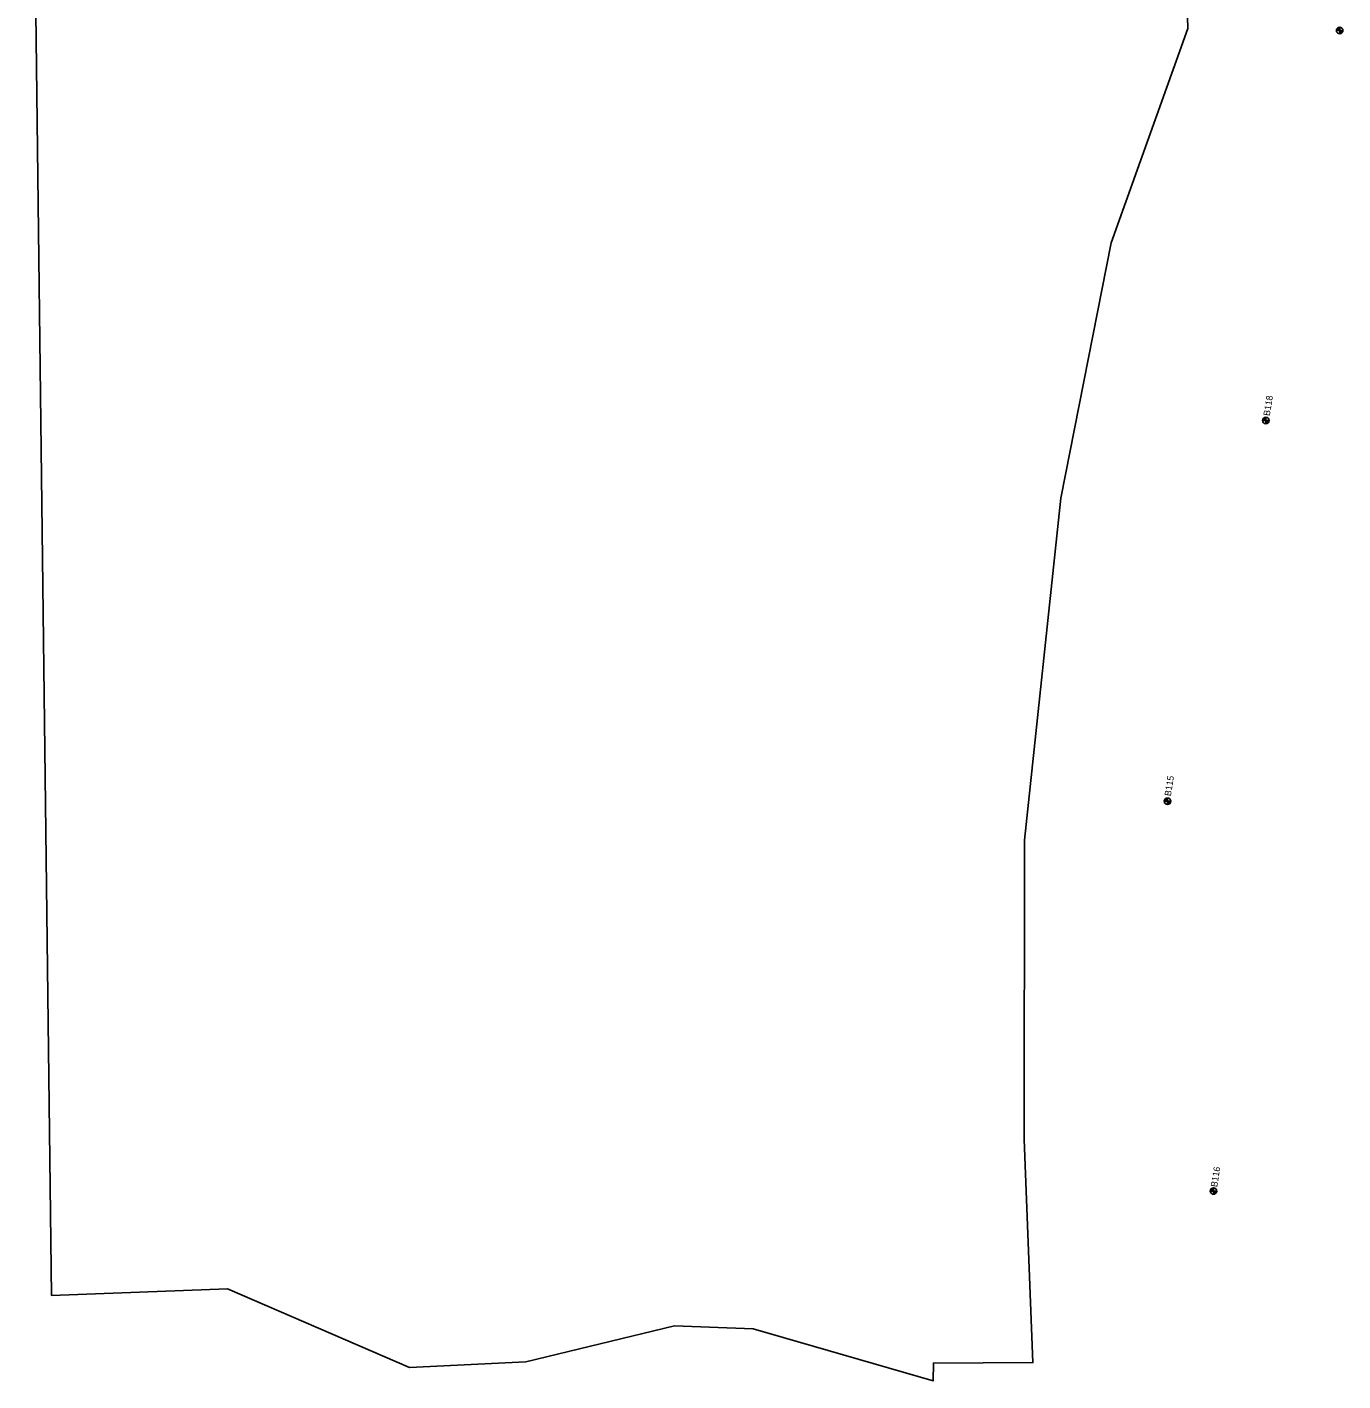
# Model space of a CAD drawing. Extents: x 331323 to 388339, y 121519 to 205315.
# Drawn here: x 353385 to 355399, y 191699 to 193771 of the extents above; entities that cross this region are included whole.
import ezdxf

# ---------------------------------------------------------------- set-up
doc = ezdxf.new("R2010")
doc.units = 0
for name, color, linetype in [('E_SOIL_BORE1 [KAPUR_CADDS_LEVELS]', 7, 'Continuous'), ('E_SOIL_BORE2 [KAPUR_CADDS_LEVELS]', 7, 'Continuous'), ('Level 21', 7, 'Continuous'), ('P_MARK', 7, 'Continuous')]:
    doc.layers.add(name, color=color, linetype=linetype)

msp = doc.modelspace()

# ---------------------------------------------------------------- linework, layer by layer
at = {"layer": 'Level 21'}
msp.add_lwpolyline([(355146.4, 194286.1), (355161.2, 193768.9), (355044, 193440.7), (354967.1, 193050.1), (354911.4, 192526.4), (354910.9, 192068.3), (354924.3, 191726.6), (354771.9, 191725.9), (354771.4, 191698.6), (354496.1, 191778.1), (354375.9, 191783.1), (354148.1, 191727.6), (353970.2, 191718.9), (353691.7, 191839.8), (353422.4, 191829.2), (353385, 194880.4)], dxfattribs=at)
at = {"layer": 'P_MARK'}
for p, q in [((355388.6, 193765.9), (355398.6, 193765.9)), ((355393.6, 193770.9), (355393.6, 193760.9)), ((355280.6, 193173.8), (355280.6, 193163.8)), ((355275.6, 193168.8), (355285.6, 193168.8)), ((355125.2, 192585.9), (355135.2, 192585.9)), ((355130.2, 192590.9), (355130.2, 192580.9)), ((355200.5, 191994.3), (355200.5, 191984.3)), ((355195.5, 191989.3), (355205.5, 191989.3))]:
    msp.add_line(p, q, dxfattribs=at)
for centre in [(355393.6, 193765.9), (355280.6, 193168.8), (355130.2, 192585.9), (355200.5, 191989.3)]:
    msp.add_circle(centre, 5, dxfattribs=at)
for centre, radius, start, end in [((355393.6, 193765.9), 4.5, 89.9869, 179.9869), ((355393.6, 193765.9), 4, 89.9869, 179.9869), ((355393.6, 193765.9), 3.5, 89.9869, 179.9869), ((355393.6, 193765.9), 3, 89.9869, 179.9869), ((355393.6, 193765.9), 2.5, 89.9869, 179.9869), ((355393.6, 193765.9), 2, 89.9869, 179.9869), ((355393.6, 193765.9), 1.5, 89.9869, 179.9869), ((355393.6, 193765.9), 1, 89.9869, 179.9869), ((355393.6, 193765.9), 0.5, 89.9869, 179.9869), ((355393.6, 193765.9), 4.5, 269.9869, 359.9869), ((355393.6, 193765.9), 4, 269.9869, 359.9869), ((355393.6, 193765.9), 3.5, 269.9869, 359.9869), ((355393.6, 193765.9), 3, 269.9869, 359.9869), ((355393.6, 193765.9), 2.5, 269.9869, 359.9869), ((355393.6, 193765.9), 2, 269.9869, 359.9869), ((355393.6, 193765.9), 1.5, 269.9869, 359.9869), ((355393.6, 193765.9), 1, 269.9869, 359.9869), ((355393.6, 193765.9), 0.5, 269.9869, 359.9869), ((355280.6, 193168.8), 4.5, 89.9869, 179.9869), ((355280.6, 193168.8), 4, 89.9869, 179.9869), ((355280.6, 193168.8), 3.5, 89.9869, 179.9869), ((355280.6, 193168.8), 3, 89.9869, 179.9869), ((355280.6, 193168.8), 2.5, 89.9869, 179.9869), ((355280.6, 193168.8), 2, 89.9869, 179.9869), ((355280.6, 193168.8), 1.5, 89.9869, 179.9869), ((355280.6, 193168.8), 1, 89.9869, 179.9869), ((355280.6, 193168.8), 0.5, 89.9869, 179.9869), ((355280.6, 193168.8), 4.5, 269.9869, 359.9869), ((355280.6, 193168.8), 4, 269.9869, 359.9869), ((355280.6, 193168.8), 3.5, 269.9869, 359.9869), ((355280.6, 193168.8), 3, 269.9869, 359.9869), ((355280.6, 193168.8), 2.5, 269.9869, 359.9869), ((355280.6, 193168.8), 2, 269.9869, 359.9869), ((355280.6, 193168.8), 1.5, 269.9869, 359.9869), ((355280.6, 193168.8), 1, 269.9869, 359.9869), ((355280.6, 193168.8), 0.5, 269.9869, 359.9869), ((355130.2, 192585.9), 4.5, 89.9869, 179.9869), ((355130.2, 192585.9), 4, 89.9869, 179.9869), ((355130.2, 192585.9), 3.5, 89.9869, 179.9869), ((355130.2, 192585.9), 3, 89.9869, 179.9869), ((355130.2, 192585.9), 2.5, 89.9869, 179.9869), ((355130.2, 192585.9), 2, 89.9869, 179.9869), ((355130.2, 192585.9), 1.5, 89.9869, 179.9869), ((355130.2, 192585.9), 1, 89.9869, 179.9869), ((355130.2, 192585.9), 0.5, 89.9869, 179.9869), ((355130.2, 192585.9), 4.5, 269.9869, 359.9869), ((355130.2, 192585.9), 4, 269.9869, 359.9869), ((355130.2, 192585.9), 3.5, 269.9869, 359.9869), ((355130.2, 192585.9), 3, 269.9869, 359.9869), ((355130.2, 192585.9), 2.5, 269.9869, 359.9869), ((355130.2, 192585.9), 2, 269.9869, 359.9869), ((355130.2, 192585.9), 1.5, 269.9869, 359.9869), ((355130.2, 192585.9), 1, 269.9869, 359.9869), ((355130.2, 192585.9), 0.5, 269.9869, 359.9869), ((355200.5, 191989.3), 4.5, 89.9869, 179.9869), ((355200.5, 191989.3), 4, 89.9869, 179.9869), ((355200.5, 191989.3), 3.5, 89.9869, 179.9869), ((355200.5, 191989.3), 3, 89.9869, 179.9869), ((355200.5, 191989.3), 2.5, 89.9869, 179.9869), ((355200.5, 191989.3), 2, 89.9869, 179.9869), ((355200.5, 191989.3), 1.5, 89.9869, 179.9869), ((355200.5, 191989.3), 1, 89.9869, 179.9869), ((355200.5, 191989.3), 0.5, 89.9869, 179.9869), ((355200.5, 191989.3), 4.5, 269.9869, 359.9869), ((355200.5, 191989.3), 4, 269.9869, 359.9869), ((355200.5, 191989.3), 3.5, 269.9869, 359.9869), ((355200.5, 191989.3), 3, 269.9869, 359.9869), ((355200.5, 191989.3), 2.5, 269.9869, 359.9869), ((355200.5, 191989.3), 2, 269.9869, 359.9869), ((355200.5, 191989.3), 1.5, 269.9869, 359.9869), ((355200.5, 191989.3), 1, 269.9869, 359.9869), ((355200.5, 191989.3), 0.5, 269.9869, 359.9869)]:
    msp.add_arc(centre, radius, start, end, dxfattribs=at)

# ---------------------------------------------------------------- texts
at = {"layer": 'E_SOIL_BORE1 [KAPUR_CADDS_LEVELS]'}
for s, p in [('B118', (355286.6, 193175.3)), ('B115', (355135.3, 192593.3))]:
    msp.add_text(s, height=10, rotation=80.9358, dxfattribs=at).set_placement(p)
at = {"layer": 'E_SOIL_BORE2 [KAPUR_CADDS_LEVELS]'}
msp.add_text('B116', height=10, rotation=80.9358, dxfattribs=at).set_placement((355206.1, 191994.8))

doc.saveas('drawing.dxf')
